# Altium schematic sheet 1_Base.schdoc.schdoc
size 309 x 223 mm; Symbol: Sheet-Symbol_A4; Device: Sheet-Symbol_A4; Company: Velizy Astro Club; Drawed: Paul V.; Reviewed: Denis G.; Version: V1.1; Page Size: A4; @Project Name: AstrAlim; @Page Count: 2; @Update Date: 2024-04-21; @Create Date: 2024-02-04; @Schematic Name: AstrAlim SCH; Part Number: AstrAlim-v1.1; @Page No: 1; @Page Name: Base
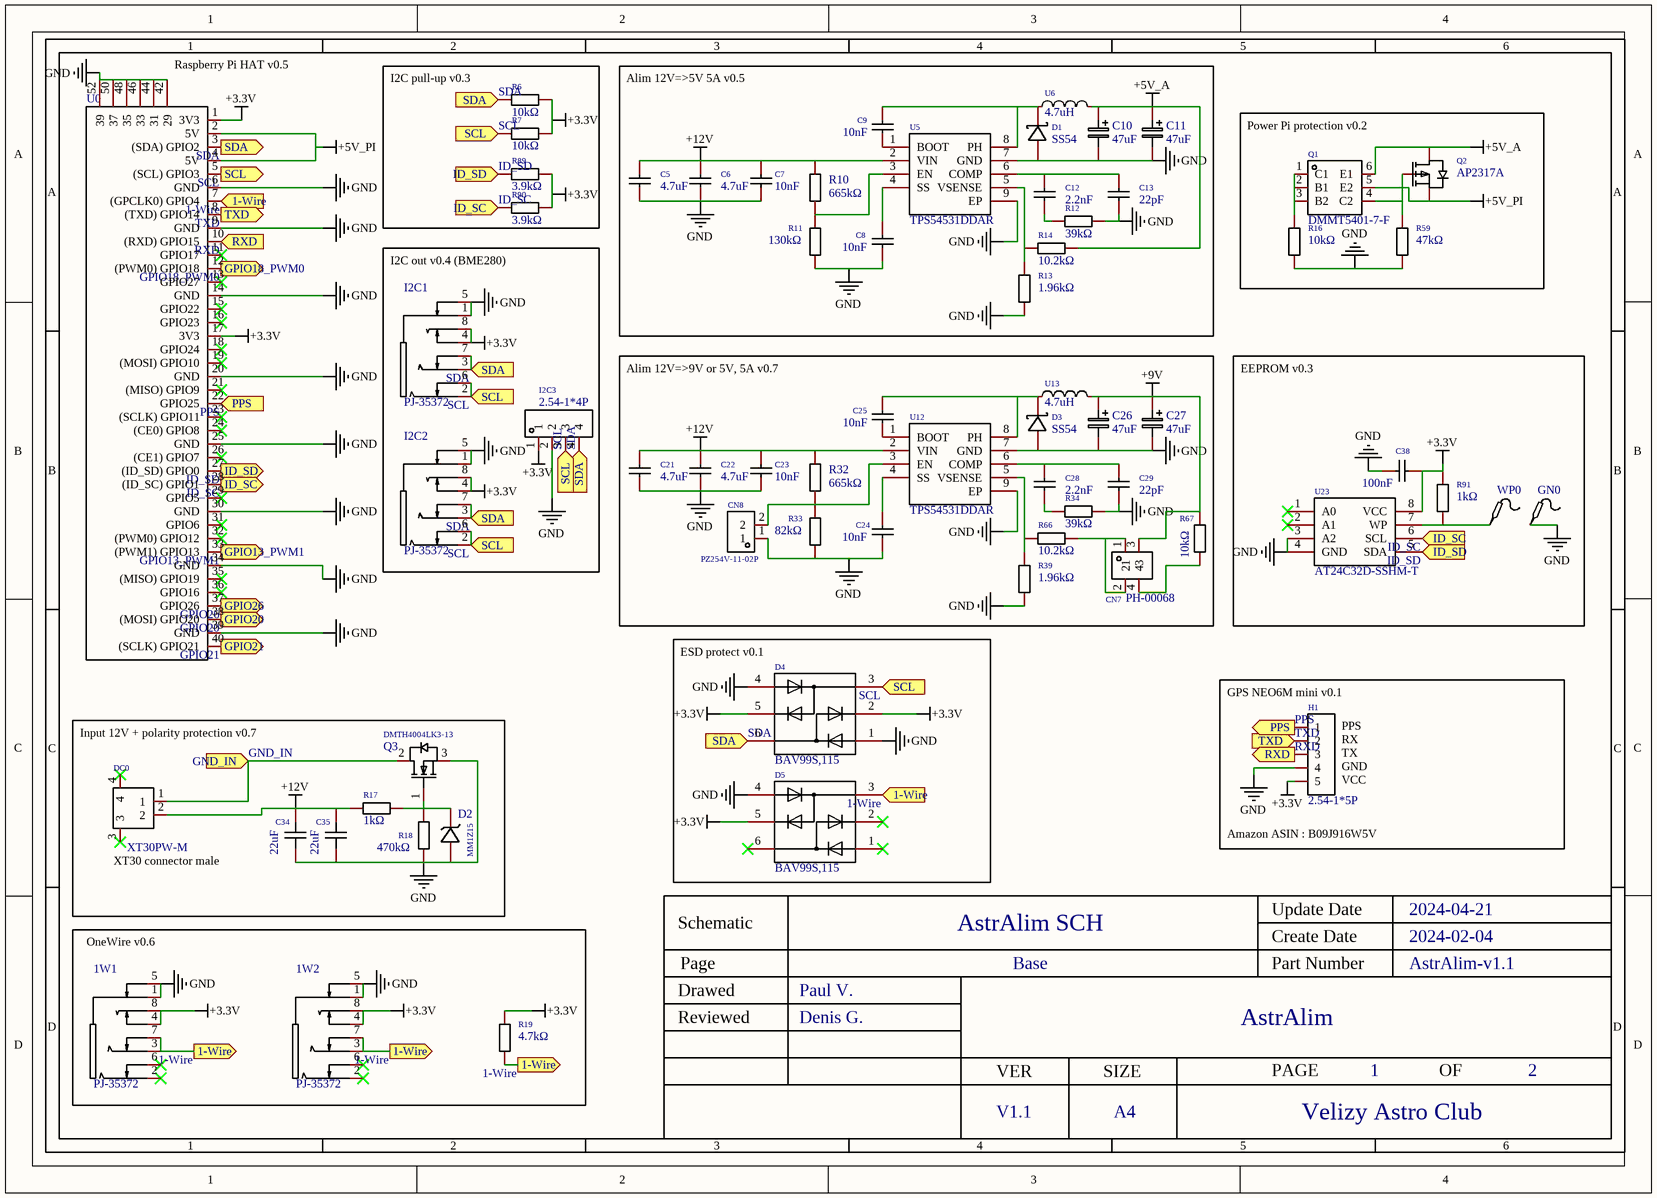
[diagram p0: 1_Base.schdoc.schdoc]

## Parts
1W1  PJ-35372  [AUDIO-TH_PJ-35372]
1W2  PJ-35372  [AUDIO-TH_PJ-35372]
C5  4.7uF  [C0805]
C6  4.7uF  [C0805]
C7  10nF  [C0402]
C8  10nF  [C0402]
C9  10nF  [C0402]
C10  47uF  [CAP-SMD_L3.5-W2.8-R-RD]
C11  47uF  [CAP-SMD_L3.5-W2.8-R-RD]
C12  2.2nF  [C0603]
C13  22pF  [C0402]
C21  4.7uF  [C0805]
C22  4.7uF  [C0805]
C23  10nF  [C0402]
C24  10nF  [C0402]
C25  10nF  [C0402]
C26  47uF  [CAP-SMD_L3.5-W2.8-R-RD]
C27  47uF  [CAP-SMD_L3.5-W2.8-R-RD]
C28  2.2nF  [C0603]
C29  22pF  [C0402]
C34  22uF  [C0805]
C35  22uF  [C0805]
C38  100nF  [C0402]
CN7  PH-00068  [HDR-TH_4P-P2.54-V-M-R2-C2-S2.54]
CN8  PZ254V-11-02P  [HDR-TH_2P-P2.54-V-M]
D1  SS54  [SMA_L4.4-W2.8-LS5.4-R-RD]
D2  MM1Z15  [SOD-123_L2.7-W1.6-LS3.7-RD]
D3  SS54  [SMA_L4.4-W2.8-LS5.4-R-RD]
D4  BAV99S,115  [SOT-363_L2.0-W1.3-P0.65-LS2.1-TL]
D5  BAV99S,115  [SOT-363_L2.0-W1.3-P0.65-LS2.1-TL]
DC0  XT30PW-M  [CONN-TH_XT30PW-M]
GN0  Test-Point  [Test-Point-0.5mm]  (value not drawn)
H1  2.54-1*5P  [HDR-TH_5P-P2.54-V-F]
I2C1  PJ-35372  [AUDIO-TH_PJ-35372]
I2C2  PJ-35372  [AUDIO-TH_PJ-35372]
I2C3  2.54-1*4P  [HDR-TH_4P-P2.54-V-F]
Q1  DMMT5401-7-F  [SOT-23-6_L2.9-W1.6-P0.95-LS2.8-BR]
Q2  AP2317A  [SOT-23-3_L2.9-W1.6-P1.90-LS2.8-BR]
Q3  DMTH4004LK3-13  [TO-252-2_L6.6-W6.1-P4.58-LS9.9-TL]
R6  10kΩ  [R0402]
R7  10kΩ  [R0402]
R10  665kΩ  [R0603]
R11  130kΩ  [R0603]
R12  39kΩ  [R0603]
R13  1.96kΩ  [R0402]
R14  10.2kΩ  [R0402]
R16  10kΩ  [R0402]
R17  1kΩ  [R0402]
R18  470kΩ  [R0603]
R19  4.7kΩ  [R0402]
R32  665kΩ  [R0603]
R33  82kΩ  [R0603]
R34  39kΩ  [R0603]
R39  1.96kΩ  [R0402]
R59  47kΩ  [R0402]
R66  10.2kΩ  [R0402]
R67  10kΩ  [R0402]
R89  3.9kΩ  [R0603]
R90  3.9kΩ  [R0603]
R91  1kΩ  [R0402]
U0  RASPI HAT FULL  [RASBERRYPI-3-HAT-EXT]  (value not drawn)
U5  TPS54531DDAR  [SOIC-8_L5.0-W4.0-P1.27-LS6.0-BL-EP2.0]
U6  4.7uH  [IND-SMD_L7.2-W6.6_GPSR07X0]
U12  TPS54531DDAR  [SOIC-8_L5.0-W4.0-P1.27-LS6.0-BL-EP2.0]
U13  4.7uH  [IND-SMD_L7.2-W6.6_GPSR07X0]
U23  AT24C32D-SSHM-T  [SOIC-8_L5.0-W4.0-P1.27-LS6.0-BL]
WP0  Test-Point  [Test-Point-0.5mm]  (value not drawn)

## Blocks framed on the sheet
I2C pull-up v0.3: R6 R7 R89 R90
Alim 12V=>5V 5A v0.5: C5-C13 D1 R10-R14 U5 U6
Power Pi protection v0.2: Q1 Q2 R16 R59
I2C out v0.4 (BME280): I2C1-I2C3
Alim 12V=>9V or 5V, 5A v0.7: C21-C29 CN7 CN8 D3 R32-R34 R39 R66 R67 U12 U13
EEPROM v0.3: C38 GN0 R91 U23 WP0
ESD protect v0.1: D4 D5
OneWire v0.6: 1W1 1W2 R19

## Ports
1-Wire (in), 1-Wire (out), GND_IN (in), GPIO13_PWM1 (out), GPIO18_PWM0 (out), GPIO20 (out), GPIO21 (out), GPIO26 (out), ID_SC (in), ID_SC (out), ID_SD (in), ID_SD (out), PPS (in), PPS (out), RXD (in), RXD (out), SCL (in), SCL (out), SDA (in), SDA (out), TXD (in), TXD (out)

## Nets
+3.3V: 1W1.4 1W1.8 1W2.4 1W2.8 C38.2 D4.2(C) D4.5(C) D5.5(C) H1.5 I2C1.4 I2C1.8 I2C2.4 I2C2.8 I2C3.1 R6.2 R7.2 R19.2 R89.2 R90.2 R91.2 U0.1(3V3) U0.17(3V3) U23.8(VCC)
+5V_A: C10.1 C11.1 Q1.6(E1) Q2.3(D) R14.2 U6.2
+5V_PI: Q1.5(E2) Q2.2(S) U0.2(5V) U0.4(5V)
+9V: C26.1 C27.1 CN7.3 R67.2 U13.2
+12V: C5.2 C6.2 C7.2 C21.2 C22.2 C23.2 C34.2 C35.2 DC0.2 R10.2 R17.1 R32.2 U5.2(VIN) U12.2(VIN)
GND: 1W1.1 1W1.5 1W2.1 1W2.5 C5.1 C6.1 C7.1 C8.1 C10.2 C11.2 C13.1 C21.1 C22.1 C23.1 C24.1 C26.2 C27.2 C29.1 C34.1 C35.1 C38.1 CN8.1 D1.1(A) D2.2(A) D3.1(A) D4.1(A) D4.4(A) D5.4(A) GN0.1 H1.4 I2C1.1 I2C1.5 I2C2.1 I2C2.5 I2C3.2 Q3.3(S) R11.1 R12.2 R13.1 R16.1 R18.1 R33.1 R34.2 R39.1 R59.1 U0.6(GND) U0.9(GND) U0.14(GND) U0.20(GND) U0.25(GND) U0.30(GND) U0.34(GND) U0.39(GND) U0.42(29) U0.44(31) U0.46(33) U0.48(35) U0.50(37) U0.52(39) U5.7(GND) U5.9(EP) U12.7(GND) U12.9(EP) U23.3(A2) U23.4(GND)
1-Wire: 1W1.3 1W1.7 1W2.3 1W2.7 D5.3(AC) R19.1 U0.7((GPCLK0)_GPIO4) ; port 1-Wire
GND_IN: DC0.1 Q3.2(D) ; port GND_IN
GPIO13_PWM1: U0.33((PWM1)_GPIO13) ; port GPIO13_PWM1
GPIO18_PWM0: U0.12((PWM0)_GPIO18) ; port GPIO18_PWM0
GPIO20: U0.38((MOSI)_GPIO20) ; port GPIO20
GPIO21: U0.40((SCLK)_GPIO21) ; port GPIO21
GPIO26: U0.37(GPIO26) ; port GPIO26
ID_SC: R90.1 U0.28((ID_SC)_GPIO1) U23.6(SCL) ; port ID_SC
ID_SD: R89.1 U0.27((ID_SD)_GPIO0) U23.5(SDA) ; port ID_SD
PPS: H1.1 U0.22(GPIO25) ; port PPS
RXD: H1.3 U0.10((RXD)_GPIO15) ; port RXD
SCL: D4.3(AC) I2C1.2 I2C1.6 I2C2.2 I2C2.6 I2C3.3 R7.1 U0.5((SCL)_GPIO3) ; port SCL
SDA: D4.6(AC) I2C1.3 I2C1.7 I2C2.3 I2C2.7 I2C3.4 R6.1 U0.3((SDA)_GPIO2) ; port SDA
TXD: H1.2 U0.8((TXD)_GPIO14) ; port TXD
NetC8_2: C8.2 U5.4(SS)
NetC9_1: C9.1 U5.1(BOOT)
NetC9_2: C9.2 D1.2(K) U5.8(PH) U6.1
NetC12_1: C12.1 R12.1
NetC12_2: C12.2 C13.2 U5.6(COMP)
NetC24_2: C24.2 U12.4(SS)
NetC25_1: C25.1 U12.1(BOOT)
NetC25_2: C25.2 D3.2(K) U12.8(PH) U13.1
NetC28_1: C28.1 R34.1
NetC28_2: C28.2 C29.2 U12.6(COMP)
NetCN7_1: CN7.1 CN7.2 R66.2
NetCN7_4: CN7.4 R67.1
NetCN8_2: CN8.2 R32.1 R33.2 U12.3(EN)
NetD2_1: D2.1(C) Q3.1(G) R17.2 R18.2
NetQ1_1: Q1.1(C1) Q1.2(B1) Q1.3(B2) R16.2
NetQ1_4: Q1.4(C2) Q2.1(G) R59.2
NetR10_1: R10.1 R11.2 U5.3(EN)
NetR13_2: R13.2 R14.1 U5.5(VSENSE)
NetR39_2: R39.2 R66.1 U12.5(VSENSE)
NetR91_1: R91.1 U23.7(WP) WP0.1

Not connected (* = marked no-connect by the designer): 1W1 2* 6*; 1W2 2* 6*; D5 1(A)* 2(C)* 6(AC)*; DC0 3* 4*; U0 11(GPIO17)* 13(GPIO27)* 15(GPIO22)* 16(GPIO23)* 18(GPIO24)* 19((MOSI)_GPIO10)* 21((MISO)_GPIO9)* 23((SCLK)_GPIO11)* 24((CE0)_GPIO8)* 26((CE1)_GPIO7)* 29(GPIO5)* 31(GPIO6)* 32((PWM0)_GPIO12)* 35((MISO)_GPIO19)* 36(GPIO16)*; U23 1(A0)* 2(A1)*

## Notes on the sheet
- (near U0) Raspberry Pi HAT v0.5
- (near DC0) Input 12V + polarity protection v0.7
- (near H1) GPS NEO6M mini v0.1
- (near H1) PPS
- (near H1) RX
- (near H1) TX
- (near H1) GND
- (near H1) VCC
- (near DC0) XT30 connector male
- (near H1) Amazon ASIN :	B09J916W5V

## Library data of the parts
1W1 1W2 I2C1 I2C2 = PJ-35372: Manufacturer: XKB Connectivity(中国星坤); Add into BOM: yes; Connector Type: 3.5mm耳机座; Current Rating (Max): 0.5A; Voltage Rating (Max): 30V; Welding Temperature (Max): 235℃; Description: Connector Type:3.5mm耳机座 Current Rating (Max):0.5A Voltage Rating (Max):30V Operating Temperature Range:-20℃~+70℃ Operating Temperature Range:-20℃~+70℃ Welding Temperature (Max):235℃
C5 C6 C21 C22 = CL21A475KAQNNNE: Manufacturer: SAMSUNG(三星); Add into BOM: yes; Tolerance: ±10%; Description: Capacitance: Tolerance:±10% Tolerance:±10% Voltage Rated: Temperature Coefficient:
C7-C9 C23-C25 = CL05B103KB5NNNC: Manufacturer: SAMSUNG(三星); Add into BOM: yes; Tolerance: ±10%; Description: Capacitance: Tolerance:±10% Tolerance:±10% Voltage Rated: Temperature Coefficient:
C10 C11 C26 C27 = CA45-B-16V-47uF-K: Manufacturer: CEC(振华新云); Add into BOM: yes; Tolerance: ±10%; Equivalent Series Resistance(ESR): 3Ω@100kHz; Description: Capacitance: Tolerance:±10% Tolerance:±10% Rated Voltage: Equivalent Series Resistance(ESR):3Ω@100kHz Operating Temperature:-55℃~+125℃ Operating Temperature:-55℃~+125℃
C12 C28 = 0603B222K500NT: Manufacturer: FH(风华); Add into BOM: yes; Tolerance: ±10%; Description: Capacitance: Tolerance:±10% Tolerance:±10% Voltage Rated: Temperature Coefficient:
C13 C29 = 0402CG220J500NT: Manufacturer: FH(风华); Add into BOM: yes; Tolerance: ±5%; Description: Capacitance: Tolerance:±5% Tolerance:±5% Voltage Rated: Temperature Coefficient:
C34 C35 = CL21A226MAQNNNE_C45783: Manufacturer: SAMSUNG(三星); Add into BOM: yes; Tolerance: ±20%; Description: Capacitance: Tolerance:±20% Tolerance:±20% Voltage Rated: Temperature Coefficient:
C38 = CL05B104KO5NNNC: Manufacturer: SAMSUNG(三星); Add into BOM: yes; Tolerance: ±10%; Description: Capacitance: Tolerance:±10% Tolerance:±10% Voltage Rated: Temperature Coefficient:
CN7 = PH-00068: Manufacturer: Liansheng(连盛); Add into BOM: no; Convert to PCB: yes; Pin Structure: 2x2P; Pitch: 2.54mm; Circluar Pins/Square Pins: Square Pins; Current Rating (Max): 3A; Description: Pin Structure:2x2P Pitch:2.54mm Number of Pins:4P Mounting Type:Straight Number of Rows:双排 Row Spacing:2.54mm Circluar Pins/Square Pins:Square Pins Current Rating (Max):3A Voltage Rating (Max):- Length of Mating Pin:6mm Insulation Height:2.5mm Length of E
CN8 = PZ254V-11-02P: Manufacturer: XFCN(兴飞); Add into BOM: no; Convert to PCB: yes; Pitch: 2.54mm; Pin Structure: 1x2P; Circluar Pins/Square Pins: Square Pins; Description: Number of Rows:Plugin Number of Pins:2P Pitch:2.54mm Pin Structure:1x2P Row Spacing:- Mounting Type:Straight Circluar Pins/Square Pins:Square Pins Current Rating (Max):- Voltage Rating (Max):- Length of Mating Pin:6mm Insulation Height:2.5mm Length of End
D1 D3 = SS54_C22452: Manufacturer: MDD; Add into BOM: yes; Forward Voltage (Vf@If): 550mV@5A; Reverse Voltage (Vr): 40V; Average Rectified Current (Io): 5A; Reverse Leakage Current (Ir): 1mA@40V; Description: Forward Voltage (Vf@If):550mV@5A Reverse Voltage (Vr):40V Average Rectified Current (Io):5A Reverse Leakage Current (Ir):1mA@40V
D2 = MM1Z15_C86235: Manufacturer: ST(先科); Add into BOM: yes; Diode Configuration: Single; Zener Voltage (Nom): 15V; Zener Voltage (Range): 13.8V~15.6V; Tolerance: ±5%; Power Dissipation: 500mW; Reverse Leakage Current (Ir): 100nA@11V; Zener Impedance (Zzt): 40Ω; Description: Diode Configuration:Single Zener Voltage (Nom):15V Zener Voltage (Range):13.8V~15.6V Zener Voltage (Range):13.8V~15.6V Tolerance:±5% Tolerance:±5% Power Dissipation:500mW Reverse Leakage Current (Ir):100nA@11V Zener Impedance (Zzt):40Ω
D4 D5 = BAV99S,115: Manufacturer: Nexperia(安世); Symbol: BAV99S,135; Add into BOM: yes; Diode Configuration: 2 Pair Series Connection; Forward Voltage (Vf@If): 1.25V@150mA; Reverse Leakage Current: 500nA@80V; Description: Diode Configuration:2 Pair Series Connection Forward Voltage (Vf@If):1.25V@150mA Reverse Voltage (Vr): Average Rectified Current (Io): Power Dissipation: Reverse Leakage Current:500nA@80V Reverse Recovery Time (trr): Operating Temperature:- Operating Temp
DC0 = XT30PW-M: Manufacturer: AMASS(艾迈斯); Add into BOM: no; Convert to PCB: yes; Brand: 艾迈斯; RatedVoltage: DC 500V; InterfaceType: 公头; RatedCurrent: 15A; RecommendedWireGauge: 16/18/20AWG; contact resistance: 1.2mΩ; specifications: 2pin; Description: Brand:艾迈斯 Model:XT30PW-M Power:- Output:- Input:- Size:- Interface:- Type:- Colour:- MaximumCurrent:- Type:航模插头 RatedVoltage:DC 500V Type1:- NumberOfUSBHoles:- InterfaceType:公头 MetalMaterial:- InsulationMaterial:- RatedCurrent:15A RecommendedWireGauge:16/
GN0 WP0 = Test-Point: Add into BOM: yes; Description: Test Point 测试点
H1 = 2.54-1*5P母: Manufacturer: BOOMELE(博穆精密); Symbol: Header-Female-2.54_1x5; Add into BOM: no; Convert to PCB: yes; Number of Holes: 5P; Pitch: 2.54mm; Holes Structure: 1x5P; Description: Number of Rows:Plugin Number of Holes:5P Pitch:2.54mm Holes Structure:1x5P Row Spacing:- Mounting Type:Straight Insulation Height:- Contact Material:- Contact Plating:-
I2C3 = 2.54-1*4P母: Manufacturer: BOOMELE(博穆精密); Add into BOM: no; Convert to PCB: yes; Holes Structure: 1x4P; Pitch: 2.54mm; Circular Hole / Square Hole: Square Holes; Number of Holes: 4P; Current Rating (Max): 3A; Holes Direction: Top; Description: Holes Structure:1x4P Pitch:2.54mm Row Spacing:- Circular Hole / Square Hole:Square Holes Mounting Type:Straight Number of Rows:Plugin Number of Holes:4P Current Rating (Max):3A Voltage Rating (Max):- Holes Direction:Top Insulation Height:- Contact Materia
Q1 = DMMT5401-7-F: Manufacturer: DIODES(美台); Add into BOM: yes; DC Current Gain (hFE@Ic,Vce): 60@10mA,5V; Transition Frequency (fT): 100MHz; Collector Cut-Off Current (Icbo): 50nA; Collector-Emitter Saturation Voltage (VCE(sat)@Ic,Ib): 500mV@50mA,5mA; Description: Transistor Type: Collector Current (Ic): Collector-Emitter Breakdown Voltage (Vceo): Power Dissipation (Pd): DC Current Gain (hFE@Ic,Vce):60@10mA,5V DC Current Gain (hFE@Ic,Vce):60@10mA,5V Transition Frequency (fT):100MHz Collector Cut-Off Current (Icbo):
Q2 = AP2317A: Manufacturer: ALLPOWER(铨力); Add into BOM: yes; Drain Source On Resistance (RDS(on)@Vgs,Id): 17mΩ@4.5V,6A; Gate Threshold Voltage (Vgs(th)@Id): 550mV@250uA; Total Gate Charge (Qg@Vgs): 19.5nC@4.5V; Input Capacitance (Ciss@Vds): 1.73nF@6V; Reverse Transfer Capacitance (Crss@Vds): 210pF@6V; Description: Type: Drain Source Voltage (Vdss): Continuous Drain Current (Id): Power Dissipation (Pd): Drain Source On Resistance (RDS(on)@Vgs,Id):17mΩ@4.5V,6A Gate Threshold Voltage (Vgs(th)@Id):550mV@250uA Total Gate Charge (Qg@Vgs):19.5nC@4.5V Input Capacitance (Ci
Q3 = DMTH4004LK3-13: Manufacturer: DIODES(美台); Add into BOM: yes; Power Dissipation (Pd): ；; Drain Source On Resistance (RDS(on)@Vgs,Id): 3mΩ@10V,50A; Gate Threshold Voltage (Vgs(th)@Id): 3V@250uA; Total Gate Charge (Qg@Vgs): 83nC@10V; Input Capacitance (Ciss@Vds): 4.45nF@25V; Description: Type: Drain Source Voltage (Vdss): Continuous Drain Current (Id): Power Dissipation (Pd):； Drain Source On Resistance (RDS(on)@Vgs,Id):3mΩ@10V,50A Gate Threshold Voltage (Vgs(th)@Id):3V@250uA Total Gate Charge (Qg@Vgs):83nC@10V Input Capacitance (Ciss@Vds
R6 R7 R16 R67 = 0402WGF1002TCE: Manufacturer: UNI-ROYAL(厚声); Add into BOM: yes; Tolerance: ±1%; Temperature Coefficient: ±100ppm/℃; Description: Resistance:10000Ω Tolerance:±1% Tolerance:±1% Power(Watts): Overload Voltage (Max): Temperature Coefficient:±100ppm/℃ Temperature Coefficient:±100ppm/℃ Type:Thick Film Resistors Operating Temperature Range:-55℃~+155℃ Operating Temperature Range:-55℃~+155℃
R10 R32 = AC0603FR-07665KL: Manufacturer: YAGEO(国巨); Add into BOM: yes; Tolerance: ±1%; Temperature Coefficient: ±100ppm/℃; Description: Type:Thick Film Resistors Resistance: Tolerance:±1% Tolerance:±1% Power(Watts): Temperature Coefficient:±100ppm/℃ Temperature Coefficient:±100ppm/℃ Overload Voltage (Max): Operating Temperature Range:-55℃~+155℃ Operating Temperature Range:-55℃~+155℃
R11 = 0603WAF1303T5E: Manufacturer: UNI-ROYAL(厚声); Add into BOM: yes; Tolerance: ±1%; Temperature Coefficient: ±100ppm/℃; Description: Resistance:130000Ω Tolerance:±1% Tolerance:±1% Power(Watts): Overload Voltage (Max): Temperature Coefficient:±100ppm/℃ Temperature Coefficient:±100ppm/℃ Type:Thick Film Resistors Operating Temperature Range:-55℃~+155℃ Operating Temperature Range:-55℃~+155
R12 R34 = 0603WAF3902T5E: Manufacturer: UNI-ROYAL(厚声); Add into BOM: yes; Tolerance: ±1%; Temperature Coefficient: ±100ppm/℃; Description: Resistance:39000Ω Tolerance:±1% Tolerance:±1% Power(Watts): Overload Voltage (Max): Temperature Coefficient:±100ppm/℃ Temperature Coefficient:±100ppm/℃ Type:Thick Film Resistors Operating Temperature Range:-55℃~+155℃ Operating Temperature Range:-55℃~+155℃
R13 R39 = 0402WGF1961TCE: Manufacturer: UNI-ROYAL(厚声); Add into BOM: yes; Tolerance: ±1%; Temperature Coefficient: ±100ppm/℃; Description: Resistance:1960Ω Tolerance:±1% Tolerance:±1% Power(Watts): Overload Voltage (Max): Temperature Coefficient:±100ppm/℃ Temperature Coefficient:±100ppm/℃ Type:Thick Film Resistors Operating Temperature Range:-55℃~+155℃ Operating Temperature Range:-55℃~+155℃
R14 R66 = 0402WGF1022TCE: Manufacturer: UNI-ROYAL(厚声); Add into BOM: yes; Tolerance: ±1%; Temperature Coefficient: ±100ppm/℃; Description: Resistance:10200Ω Tolerance:±1% Tolerance:±1% Power(Watts): Overload Voltage (Max): Temperature Coefficient:±100ppm/℃ Temperature Coefficient:±100ppm/℃ Type:Thick Film Resistors Operating Temperature Range:-55℃~+155℃ Operating Temperature Range:-55℃~+155℃
R17 R91 = 0402WGF1001TCE: Manufacturer: UNI-ROYAL(厚声); Add into BOM: yes; Tolerance: ±1%; Temperature Coefficient: ±100ppm/℃; Description: Resistance:1000Ω Tolerance:±1% Tolerance:±1% Power(Watts): Overload Voltage (Max): Temperature Coefficient:±100ppm/℃ Temperature Coefficient:±100ppm/℃ Type:Thick Film Resistors Operating Temperature Range:-55℃~+155℃ Operating Temperature Range:-55℃~+155℃
R18 = 0603WAF4703T5E: Manufacturer: UNI-ROYAL(厚声); Add into BOM: yes; Tolerance: ±1%; Temperature Coefficient: ±100ppm/℃; Description: Resistance:470000Ω Tolerance:±1% Tolerance:±1% Power(Watts): Overload Voltage (Max): Temperature Coefficient:±100ppm/℃ Temperature Coefficient:±100ppm/℃ Type:Thick Film Resistors Operating Temperature Range:-55℃~+155℃ Operating Temperature Range:-55℃~+155
R19 = 0402WGF4701TCE: Manufacturer: UNI-ROYAL(厚声); Add into BOM: yes; Tolerance: ±1%; Temperature Coefficient: ±100ppm/℃; Description: Resistance:4700Ω Tolerance:±1% Tolerance:±1% Power(Watts): Overload Voltage (Max): Temperature Coefficient:±100ppm/℃ Temperature Coefficient:±100ppm/℃ Type:Thick Film Resistors Operating Temperature Range:-55℃~+155℃ Operating Temperature Range:-55℃~+155℃
R33 = 0603WAF8202T5E: Manufacturer: UNI-ROYAL(厚声); Add into BOM: yes; Tolerance: ±1%; Temperature Coefficient: ±100ppm/℃; Description: Resistance:82000Ω Tolerance:±1% Tolerance:±1% Power(Watts): Overload Voltage (Max): Temperature Coefficient:±100ppm/℃ Temperature Coefficient:±100ppm/℃ Type:Thick Film Resistors Operating Temperature Range:-55℃~+155℃ Operating Temperature Range:-55℃~+155℃
R59 = 0402WGF4702TCE: Manufacturer: UNI-ROYAL(厚声); Add into BOM: yes; Tolerance: ±1%; Temperature Coefficient: ±100ppm/℃; Description: Resistance:47000Ω Tolerance:±1% Tolerance:±1% Power(Watts): Overload Voltage (Max): Temperature Coefficient:±100ppm/℃ Temperature Coefficient:±100ppm/℃ Type:Thick Film Resistors Operating Temperature Range:-55℃~+155℃ Operating Temperature Range:-55℃~+155℃
R89 R90 = 0603WAF3901T5E: Manufacturer: UNI-ROYAL(厚声); Add into BOM: yes; Tolerance: ±1%; Temperature Coefficient: ±100ppm/℃; Description: Resistance:3900Ω Tolerance:±1% Tolerance:±1% Power(Watts): Overload Voltage (Max): Temperature Coefficient:±100ppm/℃ Temperature Coefficient:±100ppm/℃ Type:Thick Film Resistors Operating Temperature Range:-55℃~+155℃ Operating Temperature Range:-55℃~+155℃
U0 = RASPI HAT FULL - NO OUTLINE: Manufacturer Part: RaspberryPi 3; Convert to PCB: yes; Add into BOM: no
U5 U12 = TPS54531DDAR: Manufacturer: TI(德州仪器); Add into BOM: yes; Function: Step-down type; Synchronous Rectification: NO; Output Type: Adjustable; Number of Outputs: 1; Topology: Step-down; Input Voltage: 3.5V~28V; Output Voltage: 0.8V~26.04V; Output Current (Max): 5A; Switching Frequency: 570kHz; Description: Function:Step-down type Synchronous Rectification:NO Output Type:Adjustable Number of Outputs:1 Topology:Step-down Input Voltage:3.5V~28V Input Voltage:3.5V~28V Output Voltage:0.8V~26.04V Output Voltage:0.8V~26.04V Output Current (Max):5A Switching Freque
U6 U13 = CYA0630-4.7UH: Manufacturer: SHOU HAN(首韩); Add into BOM: yes; Tolerance: ±20%; DC Resistance (DCR): 34.5mΩ; Description: Inductance: Tolerance:±20% Tolerance:±20% Rated Current: DC Resistance (DCR):34.5mΩ
U23 = AT24C32D-SSHM-T: Manufacturer: MICROCHIP(美国微芯); Add into BOM: yes; Interface Type: I2C; Memory Size: 32Kbit; Supply Voltage: 1.7V~5.5V; Description: Interface Type:I2C Memory Size:32Kbit Supply Voltage:1.7V~5.5V Supply Voltage:1.7V~5.5V Operating Temperature:-40℃~+85℃ Operating Temperature:-40℃~+85℃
